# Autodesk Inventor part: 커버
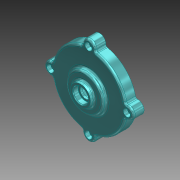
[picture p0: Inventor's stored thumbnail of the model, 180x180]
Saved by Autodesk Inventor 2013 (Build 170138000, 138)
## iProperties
Created: 2021-07
Part Number: 커버
Document SubType Name: 모델링
Designer: mdu
Material: 알루미늄 6061
Density: 2.71 g/cm^3
Mass: 196.659 g
Surface Area: 278.607 cm^2
Volume: 72.5678 cm^3
변환 표준: STEP AP214IS
파일 이름: C:\Users\SeoGD\Desktop\?쒗뿕\而ㅻ쾭-1.stp
전처리기: Build: 253, Release: 2010 SP1 - Date: Wed 07/29/2009
전송 단위: 밀리미터
불확실성: 0.01
Author: mdu
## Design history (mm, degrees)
sketch "스케치1"
  geometry: L1 (0, 0)-(0, 26); L2 (50, 0)-(50, 15); L3 (50, 15)-(25, 15); L4 (25, 15)-(25, 21); L5 (25, 21)-(15, 21); L6 (15, 21)-(13.66, 26); L7 (13.66, 26)-(10, 26); L8 (50, 0)-(45, 0); L9 (45, 0)-(45, 10); L10 (45, 10)-(14.5, 10); L11 (14.5, 10)-(13.266, 3); L12 (13.266, 3)-(11, 3); L13 (11, 3)-(11, 16); L14 (11, 16)-(7.5, 16); L15 (7.5, 16)-(7.5, 19); L16 (7.5, 19)-(10, 19); L17 (10, 19)-(10, 26)
  constraints: 34 end point, 10 parallel, 2 perpendicular, 2 point on line, 1 vertical
  dimensions: "d11" = 100 diameter of L2 L1; "d12" = 22 diameter of L13 L1; "d13" = 90 diameter of L9 L1; "d14" = 15 distance between parallel lines of L3 L8; "d15" = 10 distance between parallel lines of L8 L10; "d16" = 29 diameter of L10.end L1; "d17" = 100 deg angle of L11 L10; "d18" = 7 distance between parallel lines of L12 L10; "d19" = 13 distance between parallel lines of L14 L12; "d20" = 3 distance between parallel lines of L16 L14; "d21" = 15 diameter of L15 L1; "d22" = 20 diameter of L17 L1; "d23" = 30 diameter of L5.end L1; "d24" = 6 distance between parallel lines of L5 L3; "d25" = 50 diameter of L4 L1; "d26" = 105 deg angle of L5 L6; "d50" = 26 distance of L1.start L1.end
revolve "회전1" sketch "스케치1" stored, may be unused: angle "d27" = 90 deg
sketch "스케치2" dims "d29" = 104
  geometry: A1 r 8.5 centre (0, 52) between (8.074, 49.344) and (-8.074, 49.344); A2 r 50 centre (0, 0) between (-8.074, 49.344) and (8.074, 49.344) reference; 2 further points
  constraints: 4 point on circle, 2 vertical alignment, 1 centre point, 1 coincident, 2 other
  dimensions: "d28" = 17 diameter of A1
extrude "돌출1" join sketch "스케치2" stored distance "d30" = 10; taper "d31" = 0 deg
fillet "모깎기3" dims "d32" = 3
fillet "모깎기4" dims "d45" = 3, "d46" = 0.2
chamfer "모따기1" distance "d47" = 1; stored, may be unused: second distance "d48" = 2, angle "d49" = 45 deg
hole "구멍2" diameter "d38" = 5.5; stored, may be unused: countersink angle "d42" = 90 deg, drill point angle "d44" = 118 deg; dims "d36" = 10, "d37" = 10, "d39" = 6, "d40" = 9.5, "d41" = 5.4, "d43" = 8
node "솔리드1"
node "솔리드 본체"
node "곡면 본체"
pattern_circular "원형 패턴1" dims angle "d34" = 360 deg
pattern_circular "원형 패턴2" dims angle "d52" = 360 deg
node "솔리드2"
